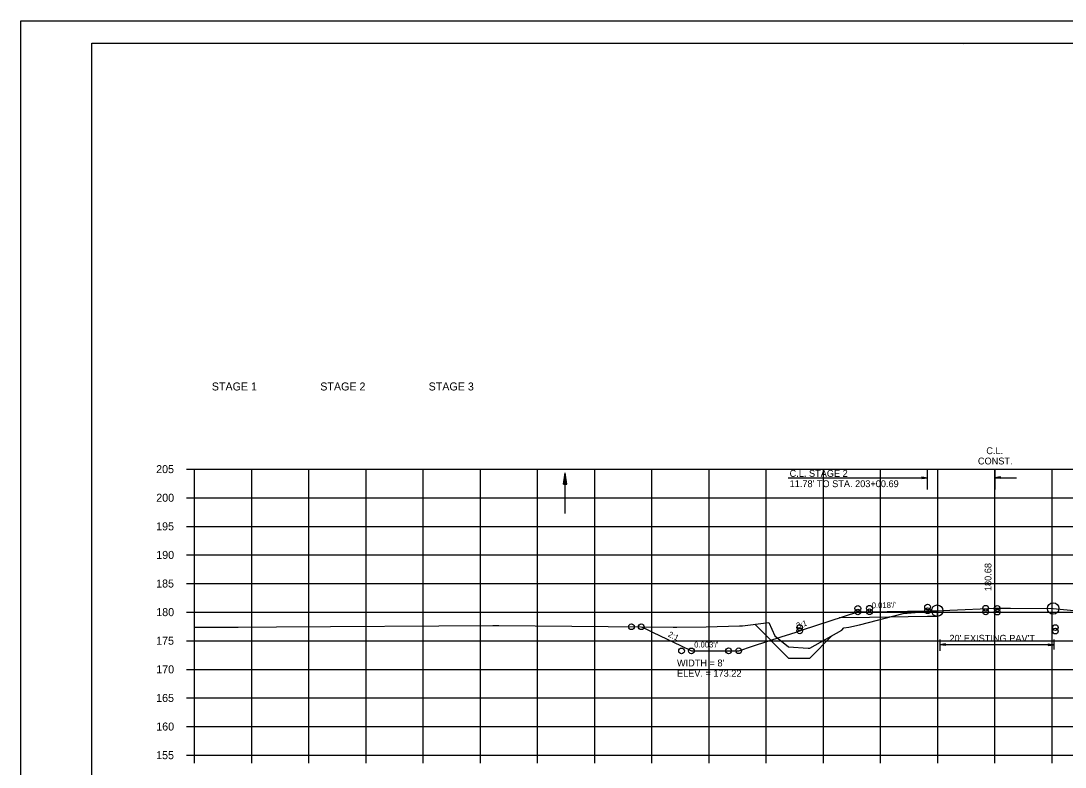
# Model space of a CAD drawing. Extents: x 1372132 to 1372465, y 380083 to 381790.
# Drawn here: x 1372131.6 to 1372314.3, y 380379.7 to 380510.2 of the extents above; entities that cross this region are included whole.
import ezdxf

# ---------------------------------------------------------------- set-up
doc = ezdxf.new("R2010")
doc.units = 0
for name, color, linetype in [('R_Alt Surface', 7, 'Continuous'), ('R_Axis', 7, 'Continuous'), ('R_Axis Annot', 7, 'Continuous'), ('R_Border', 7, 'Continuous'), ('R_Dimension', 7, 'Continuous'), ('R_Draft', 7, 'Continuous'), ('R_Erosion', 7, 'Continuous'), ('R_Exist Surface', 7, 'Continuous'), ('R_Fin Surface', 7, 'Continuous'), ('R_Grid', 7, 'Continuous'), ('R_No Plot', 7, 'Continuous'), ('R_Xsect Elev', 7, 'Continuous'), ('R_Xsect Slope', 7, 'Continuous')]:
    doc.layers.add(name, color=color, linetype=linetype)

msp = doc.modelspace()

# ---------------------------------------------------------------- linework, layer by layer
at = {"layer": 'R_Alt Surface'}
msp.add_lwpolyline([(1372291.93, 380406.03), (1372290.24, 380406.06), (1372280.07, 380405.88), (1372274.79, 380405.79)], dxfattribs=at)
at = {"layer": 'R_Axis'}
for p, q in [((1372160.61, 380431.81), (1372162.01, 380431.81)), ((1372162.01, 380381.81), (1372162.01, 380431.81)), ((1372160.61, 380426.81), (1372162.01, 380426.81)), ((1372160.61, 380421.81), (1372162.01, 380421.81)), ((1372160.61, 380416.81), (1372162.01, 380416.81)), ((1372160.61, 380411.81), (1372162.01, 380411.81)), ((1372160.61, 380406.81), (1372162.01, 380406.81)), ((1372160.61, 380401.81), (1372162.01, 380401.81)), ((1372160.61, 380396.81), (1372162.01, 380396.81)), ((1372160.61, 380391.81), (1372162.01, 380391.81)), ((1372160.61, 380386.81), (1372162.01, 380386.81)), ((1372160.61, 380381.81), (1372162.01, 380381.81)), ((1372162.01, 380381.81), (1372442.01, 380381.81)), ((1372162.01, 380380.41), (1372162.01, 380381.81)), ((1372172.01, 380380.41), (1372172.01, 380381.81)), ((1372182.01, 380380.41), (1372182.01, 380381.81)), ((1372192.01, 380380.41), (1372192.01, 380381.81)), ((1372202.01, 380380.41), (1372202.01, 380381.81)), ((1372212.01, 380380.41), (1372212.01, 380381.81)), ((1372222.01, 380380.41), (1372222.01, 380381.81)), ((1372232.01, 380380.41), (1372232.01, 380381.81)), ((1372242.01, 380380.41), (1372242.01, 380381.81)), ((1372252.01, 380380.41), (1372252.01, 380381.81)), ((1372262.01, 380380.41), (1372262.01, 380381.81)), ((1372272.01, 380380.41), (1372272.01, 380381.81)), ((1372282.01, 380380.41), (1372282.01, 380381.81)), ((1372292.01, 380380.41), (1372292.01, 380381.81)), ((1372302.01, 380380.41), (1372302.01, 380381.81)), ((1372312.01, 380380.41), (1372312.01, 380381.81))]:
    msp.add_line(p, q, dxfattribs=at)
at = {"layer": 'R_Border'}
for p, q in [((1372144.01, 380506.27), (1372460.19, 380506.27)), ((1372144.01, 380300.81), (1372144.01, 380506.27)), ((1372296.53, 380506.01), (1372296.53, 380506.01)), ((1372296.53, 380506.01), (1372296.53, 380506.01))]:
    msp.add_line(p, q, dxfattribs=at)
at = {"layer": 'R_Dimension'}
for p, q in [((1372226.53, 380429.18), (1372226.83, 380431.18)), ((1372226.53, 380429.18), (1372226.83, 380431.18)), ((1372226.58, 380429.18), (1372226.83, 380430.84)), ((1372226.58, 380429.18), (1372226.83, 380430.84)), ((1372226.63, 380429.18), (1372226.83, 380430.5)), ((1372226.63, 380429.18), (1372226.83, 380430.5)), ((1372226.68, 380429.18), (1372226.83, 380430.17)), ((1372226.68, 380429.18), (1372226.83, 380430.17)), ((1372226.73, 380429.18), (1372226.83, 380429.83)), ((1372226.73, 380429.18), (1372226.83, 380429.83)), ((1372227.13, 380429.18), (1372226.83, 380431.18)), ((1372227.13, 380429.18), (1372226.83, 380431.18)), ((1372227.08, 380429.18), (1372226.83, 380430.84)), ((1372227.08, 380429.18), (1372226.83, 380430.84)), ((1372227.03, 380429.18), (1372226.83, 380430.5)), ((1372227.03, 380429.18), (1372226.83, 380430.5)), ((1372226.98, 380429.18), (1372226.83, 380430.17)), ((1372226.98, 380429.18), (1372226.83, 380430.17)), ((1372226.93, 380429.18), (1372226.83, 380429.83)), ((1372226.93, 380429.18), (1372226.83, 380429.83)), ((1372226.53, 380429.18), (1372227.13, 380429.18)), ((1372226.53, 380429.18), (1372227.13, 380429.18)), ((1372226.78, 380429.18), (1372226.83, 380429.49)), ((1372226.78, 380429.18), (1372226.83, 380429.49)), ((1372226.88, 380429.18), (1372226.83, 380429.49)), ((1372226.88, 380429.18), (1372226.83, 380429.49))]:
    msp.add_line(p, q, dxfattribs=at)
at = {"layer": 'R_Draft'}
for p, q in [((1372290.24, 380428.22), (1372290.24, 380431.81)), ((1372302.01, 380431.81), (1372302.01, 380428.22)), ((1372226.83, 380424.04), (1372226.83, 380431.18)), ((1372265.82, 380430.3), (1372290.24, 380430.3)), ((1372289.24, 380430.45), (1372290.24, 380430.3)), ((1372289.24, 380430.45), (1372289.24, 380430.15)), ((1372289.24, 380430.45), (1372290.24, 380430.3)), ((1372289.24, 380430.45), (1372289.24, 380430.15)), ((1372289.24, 380430.42), (1372290.07, 380430.3)), ((1372289.24, 380430.42), (1372290.07, 380430.3)), ((1372289.24, 380430.4), (1372289.9, 380430.3)), ((1372289.24, 380430.4), (1372289.9, 380430.3)), ((1372289.24, 380430.37), (1372289.73, 380430.3)), ((1372289.24, 380430.37), (1372289.73, 380430.3)), ((1372289.24, 380430.35), (1372289.56, 380430.3)), ((1372289.24, 380430.35), (1372289.56, 380430.3)), ((1372289.24, 380430.32), (1372289.4, 380430.3)), ((1372289.24, 380430.32), (1372289.4, 380430.3)), ((1372289.24, 380430.15), (1372290.24, 380430.3)), ((1372289.24, 380430.25), (1372289.56, 380430.3)), ((1372289.24, 380430.2), (1372289.9, 380430.3)), ((1372289.24, 380430.17), (1372290.07, 380430.3)), ((1372289.24, 380430.23), (1372289.73, 380430.3)), ((1372289.24, 380430.28), (1372289.4, 380430.3)), ((1372289.24, 380430.15), (1372290.24, 380430.3)), ((1372289.24, 380430.25), (1372289.56, 380430.3)), ((1372289.24, 380430.2), (1372289.9, 380430.3)), ((1372289.24, 380430.17), (1372290.07, 380430.3)), ((1372289.24, 380430.23), (1372289.73, 380430.3)), ((1372289.24, 380430.28), (1372289.4, 380430.3)), ((1372303.01, 380430.45), (1372302.01, 380430.3)), ((1372302.01, 380430.3), (1372305.82, 380430.3)), ((1372303.01, 380430.15), (1372302.01, 380430.3)), ((1372303.01, 380430.42), (1372302.18, 380430.3)), ((1372303.01, 380430.17), (1372302.18, 380430.3)), ((1372303.01, 380430.4), (1372302.35, 380430.3)), ((1372303.01, 380430.2), (1372302.35, 380430.3)), ((1372303.01, 380430.37), (1372302.52, 380430.3)), ((1372303.01, 380430.23), (1372302.52, 380430.3)), ((1372303.01, 380430.35), (1372302.69, 380430.3)), ((1372303.01, 380430.25), (1372302.69, 380430.3)), ((1372303.01, 380430.32), (1372302.86, 380430.3)), ((1372303.01, 380430.28), (1372302.86, 380430.3)), ((1372303.01, 380430.15), (1372303.01, 380430.45)), ((1372291.93, 380407.03), (1372291.93, 380406.03)), ((1372292.35, 380402.04), (1372292.35, 380400.03)), ((1372293.35, 380401.27), (1372292.35, 380401.12)), ((1372293.35, 380401.27), (1372292.35, 380401.12)), ((1372312.33, 380401.12), (1372292.35, 380401.12)), ((1372293.35, 380400.97), (1372292.35, 380401.12)), ((1372293.35, 380400.97), (1372292.35, 380401.12)), ((1372293.35, 380401.25), (1372292.52, 380401.12)), ((1372293.35, 380401.25), (1372292.52, 380401.12)), ((1372293.35, 380401), (1372292.52, 380401.12)), ((1372293.35, 380401), (1372292.52, 380401.12)), ((1372293.35, 380401.22), (1372292.69, 380401.12)), ((1372293.35, 380401.22), (1372292.69, 380401.12)), ((1372293.35, 380401.02), (1372292.69, 380401.12)), ((1372293.35, 380401.02), (1372292.69, 380401.12)), ((1372293.35, 380401.2), (1372292.86, 380401.12)), ((1372293.35, 380401.2), (1372292.86, 380401.12)), ((1372293.35, 380401.05), (1372292.86, 380401.12)), ((1372293.35, 380401.05), (1372292.86, 380401.12)), ((1372293.35, 380401.17), (1372293.03, 380401.12)), ((1372293.35, 380401.17), (1372293.03, 380401.12)), ((1372293.35, 380401.08), (1372293.03, 380401.12)), ((1372293.35, 380401.08), (1372293.03, 380401.12)), ((1372293.35, 380401.15), (1372293.19, 380401.12)), ((1372293.35, 380401.15), (1372293.19, 380401.12)), ((1372293.35, 380401.1), (1372293.19, 380401.12)), ((1372293.35, 380401.1), (1372293.19, 380401.12)), ((1372293.35, 380400.97), (1372293.35, 380401.27)), ((1372293.35, 380400.97), (1372293.35, 380401.27)), ((1372311.33, 380401.27), (1372312.33, 380401.12)), ((1372311.33, 380401.27), (1372311.33, 380400.97)), ((1372311.33, 380401.25), (1372312.16, 380401.12)), ((1372311.33, 380401.22), (1372311.99, 380401.12)), ((1372311.33, 380401.2), (1372311.83, 380401.12)), ((1372311.33, 380401.17), (1372311.66, 380401.12)), ((1372311.33, 380401.15), (1372311.49, 380401.12)), ((1372311.33, 380400.97), (1372312.33, 380401.12)), ((1372311.33, 380401.08), (1372311.66, 380401.12)), ((1372311.33, 380401.02), (1372311.99, 380401.12)), ((1372311.33, 380401), (1372312.16, 380401.12)), ((1372311.33, 380401.05), (1372311.83, 380401.12)), ((1372311.33, 380401.1), (1372311.49, 380401.12)), ((1372312.33, 380402.04), (1372312.33, 380400.27)), ((1372292.35, 380400.27), (1372292.35, 380400.27))]:
    msp.add_line(p, q, dxfattribs=at)
at = {"layer": 'R_Erosion'}
for p, q in [((1372265.91, 380398.78), (1372260, 380404.69)), ((1372269.61, 380398.78), (1372273.56, 380402.73)), ((1372265.91, 380398.78), (1372269.61, 380398.78))]:
    msp.add_line(p, q, dxfattribs=at)
at = {"layer": 'R_Exist Surface'}
msp.add_lwpolyline([(1372162.01, 380404.21), (1372169.61, 380404.2), (1372176.35, 380404.25), (1372214.18, 380404.49), (1372215.24, 380404.48), (1372234.33, 380404.3), (1372245.71, 380404.19), (1372246.36, 380404.2), (1372251.5, 380404.25), (1372257.32, 380404.44), (1372257.87, 380404.42), (1372262.45, 380405), (1372263.51, 380402.64), (1372265.92, 380400.77), (1372269.32, 380400.51), (1372269.61, 380400.5), (1372275.24, 380403.68), (1372275.61, 380404.05), (1372276.47, 380404.16), (1372278.3, 380404.57), (1372285.94, 380406.59), (1372288.06, 380406.76), (1372288.85, 380406.83), (1372289.47, 380406.86), (1372291.93, 380407.06), (1372294.11, 380407.15), (1372302.13, 380407.49), (1372304.77, 380407.48), (1372312.21, 380407.44), (1372316.49, 380407.01)], dxfattribs=at)
at = {"layer": 'R_Fin Surface'}
msp.add_lwpolyline([(1372240.14, 380404.25), (1372240.7, 380403.98), (1372242.21, 380403.25), (1372247.02, 380400.95), (1372248.92, 380400.03), (1372253.11, 380400.04), (1372257.19, 380400.06), (1372259.63, 380400.85), (1372264.79, 380402.53), (1372265.37, 380402.72), (1372267.26, 380403.33), (1372267.67, 380403.47), (1372267.86, 380403.53), (1372268.35, 380403.69), (1372278.03, 380406.84), (1372279.09, 380406.86), (1372280.07, 380406.88), (1372283.15, 380406.93), (1372290.24, 380407.06), (1372290.38, 380407.06), (1372291.93, 380407.03)], dxfattribs=at)
at = {"layer": 'R_Grid'}
for p, q in [((1372162.01, 380431.81), (1372442.01, 380431.81)), ((1372162.01, 380381.81), (1372162.01, 380431.81)), ((1372172.01, 380381.81), (1372172.01, 380431.81)), ((1372182.01, 380381.81), (1372182.01, 380431.81)), ((1372192.01, 380381.81), (1372192.01, 380431.81)), ((1372202.01, 380381.81), (1372202.01, 380431.81)), ((1372212.01, 380381.81), (1372212.01, 380431.81)), ((1372222.01, 380381.81), (1372222.01, 380431.81)), ((1372232.01, 380381.81), (1372232.01, 380431.81)), ((1372242.01, 380381.81), (1372242.01, 380431.81)), ((1372252.01, 380381.81), (1372252.01, 380431.81)), ((1372262.01, 380381.81), (1372262.01, 380431.81)), ((1372272.01, 380381.81), (1372272.01, 380431.81)), ((1372282.01, 380381.81), (1372282.01, 380431.81)), ((1372292.01, 380381.81), (1372292.01, 380431.81)), ((1372302.01, 380381.81), (1372302.01, 380431.81)), ((1372312.01, 380381.81), (1372312.01, 380431.81)), ((1372162.01, 380426.81), (1372442.01, 380426.81)), ((1372162.01, 380421.81), (1372442.01, 380421.81)), ((1372162.01, 380416.81), (1372442.01, 380416.81)), ((1372162.01, 380411.81), (1372442.01, 380411.81)), ((1372162.01, 380406.81), (1372442.01, 380406.81)), ((1372162.01, 380401.81), (1372442.01, 380401.81)), ((1372162.01, 380396.81), (1372442.01, 380396.81)), ((1372162.01, 380391.81), (1372442.01, 380391.81)), ((1372162.01, 380386.81), (1372442.01, 380386.81)), ((1372162.01, 380381.81), (1372442.01, 380381.81))]:
    msp.add_line(p, q, dxfattribs=at)
at = {"layer": 'R_No Plot'}
msp.add_line((1372131.61, 380510.17), (1372464.95, 380510.17), dxfattribs=at)
for points in [[(1372131.61, 380510.17), (1372464.95, 380510.17), (1372464.95, 380296.83), (1372131.61, 380296.83)], [(1372377.93, 380506.27), (1372377.93, 380496.39), (1372413.67, 380496.39), (1372413.67, 380493.47), (1372436.87, 380493.47), (1372436.87, 380469.14), (1372460.19, 380469.14), (1372460.19, 380300.81), (1372144.01, 380300.81), (1372144.01, 380506.27)]]:
    msp.add_lwpolyline(points, close=True, dxfattribs=at)
for centre, radius in [((1372278.03, 380407.46), 0.5), ((1372280.07, 380407.49), 0.5), ((1372290.24, 380407.69), 0.5), ((1372291.93, 380407.06), 1), ((1372300.4, 380407.49), 0.5), ((1372302.43, 380407.45), 0.5), ((1372312.21, 380407.44), 1), ((1372278.03, 380406.84), 0.5), ((1372280.07, 380406.88), 0.5), ((1372290.24, 380407.06), 0.5), ((1372300.4, 380406.86), 0.5), ((1372302.43, 380406.82), 0.5), ((1372238.42, 380404.26), 0.5), ((1372240.14, 380404.25), 0.5), ((1372267.86, 380404.12), 0.5), ((1372267.86, 380403.53), 0.5), ((1372312.59, 380404.12), 0.5), ((1372312.59, 380403.49), 0.5), ((1372247.19, 380400.03), 0.5), ((1372248.92, 380400.03), 0.5), ((1372255.42, 380400.05), 0.5), ((1372257.19, 380400.06), 0.5)]:
    msp.add_circle(centre, radius, dxfattribs=at)
at = {"layer": 'R_Xsect Elev'}
msp.add_line((1372302.01, 380407.49), (1372302.01, 380417.49), dxfattribs=at)

# ---------------------------------------------------------------- texts
at = {"layer": 'R_Axis Annot'}
for s, p in [('STAGE 1', (1372165.01, 380445.56)), ('STAGE 2', (1372183.98, 380445.56)), ('STAGE 3', (1372202.94, 380445.56)), ('205', (1372155.27, 380431.11)), ('200', (1372155.29, 380426.11)), ('195', (1372155.27, 380421.11)), ('190', (1372155.29, 380416.11)), ('185', (1372155.27, 380411.11)), ('180', (1372155.29, 380406.11)), ('175', (1372155.27, 380401.11)), ('170', (1372155.29, 380396.11)), ('165', (1372155.27, 380391.11)), ('160', (1372155.29, 380386.11)), ('155', (1372155.27, 380381.11))]:
    msp.add_text(s, height=1.4, dxfattribs=at).set_placement(p)
at = {"layer": 'R_Dimension'}
for s, p in [("WIDTH = 8'", (1372246.39, 380397.32)), ('ELEV. = 173.22', (1372246.39, 380395.52))]:
    msp.add_text(s, height=1.2, dxfattribs=at).set_placement(p)
at = {"layer": 'R_Draft'}
for s, p in [('C.L. ', (1372300.51, 380434.43)), ('CONST. ', (1372299.04, 380432.63)), ('C.L. STAGE 2', (1372266.1, 380430.46)), ("11.78' TO STA. 203+00.69", (1372266.1, 380428.66)), ("20' EXISTING PAV'T", (1372294.05, 380401.64))]:
    msp.add_text(s, height=1.2, rotation=360, dxfattribs=at).set_placement(p)
at = {"layer": 'R_Xsect Elev'}
msp.add_text('180.68', height=1.2, rotation=90, dxfattribs=at).set_placement((1372301.41, 380410.49))
at = {"layer": 'R_Xsect Slope'}
for s, rotation, p in [("0.018'/'", 1.0238, (1372280.48, 380407.49)), ('3:1', 18.0355, (1372267.46, 380403.93)), ('2:1', 334.3585, (1372244.74, 380402.59)), ("0.003'/'", 0.1723, (1372249.4, 380400.63))]:
    msp.add_text(s, height=1, rotation=rotation, dxfattribs=at).set_placement(p)

doc.saveas('drawing.dxf')
